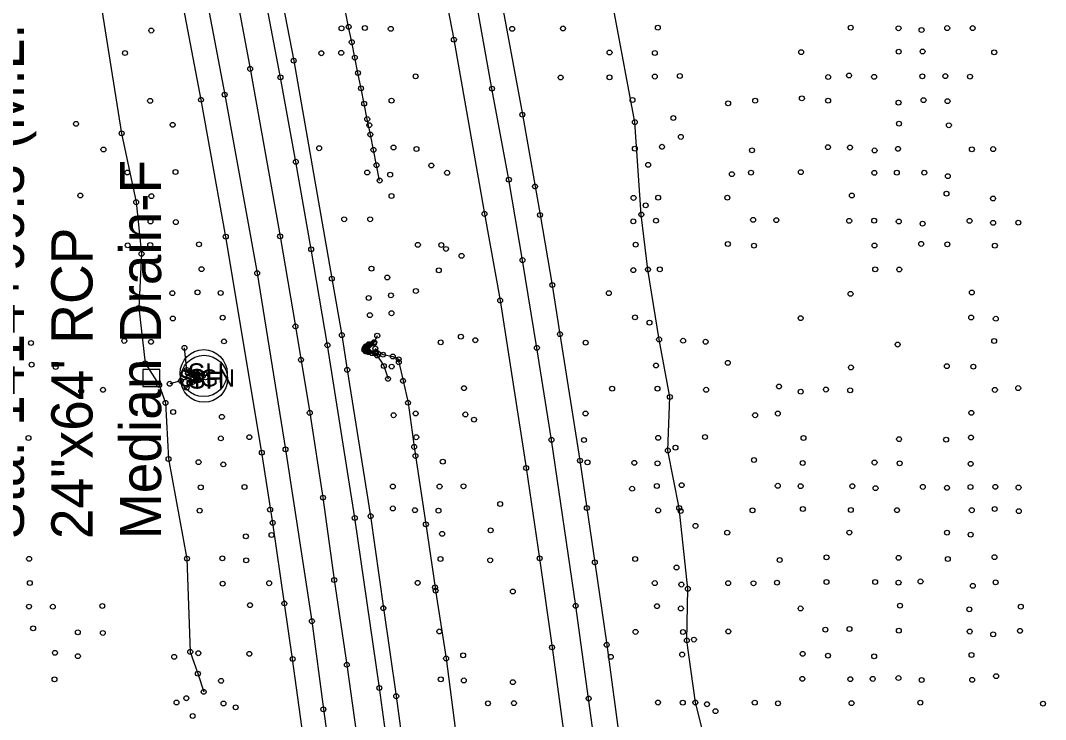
# Model space of a CAD drawing. Extents: x 20503438 to 20508873, y 7964251 to 7984667.
# Drawn here: x 20506477 to 20506895.3, y 7974142.9 to 7974428.1 of the extents above; entities that cross this region are included whole.
import ezdxf

# ---------------------------------------------------------------- set-up
doc = ezdxf.new("R2010")
doc.units = 0
for name, color, linetype in [('SurBreakLine', 7, 'Continuous'), ('SurConcreteSlab', 7, 'Continuous'), ('SurDrainageArrowDown', 7, 'Continuous'), ('SurDrainageArrowUp', 7, 'Continuous'), ('SurEdgeRoadPaved', 7, 'Continuous'), ('SurEdgeShoulderPaved', 7, 'Continuous'), ('SurNaturalCells', 7, 'Continuous'), ('SurPointsNonDTM', 7, 'Continuous'), ('SurRoadPoints', 7, 'Continuous'), ('SurSurveyPoints', 7, 'Continuous'), ('SurTxtDrainage', 7, 'Continuous')]:
    doc.layers.add(name, color=color, linetype=linetype)

msp = doc.modelspace()

# ---------------------------------------------------------------- linework, layer by layer
at = {"layer": 'SurBreakLine'}
for points in [[(20506576.27, 7974776.6), (20506593.8, 7974705.89), (20506609.82, 7974635.75), (20506617.81, 7974599.34), (20506640.03, 7974492.01), (20506653.87, 7974420.35), (20506666.37, 7974349.21), (20506672.75, 7974313.88), (20506683.34, 7974245.52), (20506688.86, 7974208.63), (20506693.93, 7974172.3), (20506703.16, 7974103.94)], [(20506496.44, 7974749.65), (20506513.28, 7974680.82), (20506521.4, 7974646.05), (20506529.3, 7974611.15), (20506530.58, 7974605.33), (20506531.23, 7974602.42), (20506534.44, 7974587.86), (20506543.23, 7974547.26), (20506549.96, 7974513.93), (20506556.42, 7974482.86), (20506563.46, 7974447), (20506570.72, 7974408.4), (20506582.94, 7974340.06), (20506589.19, 7974303.3), (20506595.05, 7974268.01), (20506600.44, 7974233.42), (20506605.04, 7974199.81), (20506610.16, 7974165.22), (20506614.11, 7974136.91)], [(20506622.58, 7974299.5), (20506621.36, 7974296.88), (20506619.19, 7974296.02), (20506617.84, 7974295.09), (20506617.44, 7974294.37), (20506617.3, 7974293.68), (20506617.98, 7974292.98), (20506620.4, 7974292.37), (20506621.98, 7974292.19), (20506622.55, 7974291.45), (20506625.26, 7974287.15), (20506626.99, 7974281.89)], [(20506544.81, 7974278.28), (20506546.06, 7974279.95), (20506548.33, 7974281.05), (20506549.46, 7974281.51), (20506552.46, 7974282.53), (20506552.02, 7974283.94), (20506549.26, 7974283.91), (20506545.43, 7974284.52), (20506544.91, 7974285.49), (20506543.93, 7974294.57)]]:
    msp.add_lwpolyline(points, dxfattribs=at)
at = {"layer": 'SurConcreteSlab'}
for points in [[(20506621.93, 7974292.81), (20506618.97, 7974293.19), (20506618.34, 7974293.51), (20506618.21, 7974294.14), (20506618.28, 7974294.84), (20506619.19, 7974295.49), (20506621.25, 7974296.4), (20506621.18, 7974296.72), (20506619.6, 7974296), (20506618.27, 7974295.21), (20506617.99, 7974294.47), (20506617.85, 7974293.91), (20506618.29, 7974293.26), (20506619.13, 7974292.81), (20506621.62, 7974292.49)], [(20506545.95, 7974280.37), (20506548.76, 7974281.72), (20506549.17, 7974282.28), (20506548.92, 7974283.14), (20506548.08, 7974283.61), (20506545.38, 7974284.07), (20506545.41, 7974284.39), (20506547.58, 7974283.97), (20506548.69, 7974283.59), (20506549.12, 7974283.1), (20506549.31, 7974282.29), (20506548.65, 7974281.39), (20506546.99, 7974280.45), (20506546.02, 7974280.06)]]:
    msp.add_lwpolyline(points, close=True, dxfattribs=at)
at = {"layer": 'SurDrainageArrowDown'}
for points in [[(20506755.78, 7974136.83), (20506752.41, 7974149.78), (20506748.94, 7974175.15), (20506749.34, 7974196.23), (20506745.81, 7974229.19), (20506741.18, 7974252.69), (20506742.02, 7974274.49), (20506737.61, 7974297.98), (20506733.07, 7974326.54), (20506730.36, 7974348.98), (20506727.7, 7974386.63), (20506719.39, 7974431.04), (20506712.14, 7974468.28), (20506707.22, 7974517.82), (20506704.55, 7974534.93), (20506693.74, 7974579.65), (20506669.12, 7974668.51), (20506657.71, 7974715.84), (20506642.35, 7974760.13)], [(20506623.56, 7974362.82), (20506622.3, 7974369.09), (20506621.03, 7974375.37), (20506619.77, 7974381.64), (20506618.51, 7974387.91), (20506617.24, 7974394.19), (20506615.98, 7974400.46), (20506614.71, 7974406.73), (20506613.45, 7974413.01), (20506612.19, 7974419.28), (20506610.92, 7974425.56), (20506609.66, 7974431.83)], [(20506545.45, 7974282.23), (20506542.47, 7974281.12), (20506537.88, 7974279.9)]]:
    msp.add_lwpolyline(points, dxfattribs=at)
at = {"layer": 'SurDrainageArrowUp'}
for points in [[(20506473.78, 7974604.66), (20506480.36, 7974587.19), (20506482.83, 7974571.94), (20506491.28, 7974529.66), (20506491.34, 7974527.7), (20506491.67, 7974526.73), (20506495.97, 7974502.65), (20506497.54, 7974495.64), (20506500.39, 7974485.96), (20506504.21, 7974460.01), (20506510.19, 7974432.48), (20506518.26, 7974382.08), (20506524.19, 7974353.98), (20506526.41, 7974332.93), (20506525.26, 7974310.82), (20506527.84, 7974288.26), (20506533.58, 7974279.38), (20506536.19, 7974272.1), (20506537.43, 7974249.2), (20506544.92, 7974208.5), (20506546.26, 7974170.48), (20506549.4, 7974161.58), (20506551.76, 7974154.15)], [(20506621.79, 7974294.22), (20506624.96, 7974291.77), (20506628.95, 7974291.01), (20506631.32, 7974289.89), (20506631.38, 7974288.67), (20506633.11, 7974281.11), (20506635.15, 7974272.15), (20506637.66, 7974254.12), (20506638.18, 7974250.44), (20506642.45, 7974222.54), (20506646.18, 7974196.79), (20506646.4, 7974195.46), (20506650.69, 7974167.8), (20506657.28, 7974117.15), (20506663.41, 7974066.36)]]:
    msp.add_lwpolyline(points, dxfattribs=at)
at = {"layer": 'SurEdgeRoadPaved'}
for points in [[(20506601.11, 7974767.59), (20506615.26, 7974710.46), (20506618.47, 7974696.62), (20506622.31, 7974680.02), (20506632.02, 7974638.07), (20506640, 7974601.83), (20506647.68, 7974566.23), (20506658.89, 7974511.83), (20506660.04, 7974506.16), (20506662.35, 7974494.84), (20506665.95, 7974475.44), (20506672.19, 7974441.86), (20506681.8, 7974389.72), (20506686.97, 7974360.38), (20506689.01, 7974348.79), (20506694.04, 7974320.19), (20506697.15, 7974300.16), (20506705.32, 7974248.53), (20506708.15, 7974229.18), (20506711.39, 7974206.99), (20506716.24, 7974173.38), (20506725.64, 7974103.3)], [(20506483.51, 7974751.12), (20506492.4, 7974715.32), (20506501, 7974680.2), (20506517.4, 7974609.46), (20506525.13, 7974573.3), (20506532.86, 7974538.45), (20506547.05, 7974468.05), (20506560.33, 7974397.87), (20506573.57, 7974325), (20506585.16, 7974253.12), (20506595.92, 7974182.98), (20506600.61, 7974147.04), (20506605.6, 7974111.5)], [(20506596.29, 7974107.44), (20506588.06, 7974167.58), (20506584.67, 7974190.25), (20506579.93, 7974223.1), (20506575.49, 7974251.78), (20506560.77, 7974339.91), (20506550.66, 7974395.81), (20506534.83, 7974479.46), (20506523.72, 7974534.35), (20506517.1, 7974564.53), (20506511.57, 7974590.47), (20506503.36, 7974626.26), (20506497.68, 7974651.01), (20506492.26, 7974674.18), (20506484.05, 7974708.49), (20506482.06, 7974716.57), (20506481.39, 7974719.26)], [(20506628.34, 7974119.83), (20506623.44, 7974155.73), (20506613.41, 7974225.13), (20506602.26, 7974295.62), (20506595.62, 7974334.77), (20506589.36, 7974370.49), (20506583.07, 7974404.95), (20506570.23, 7974472.96), (20506555.99, 7974542.36), (20506548.57, 7974577.73), (20506532.64, 7974648.96), (20506516.06, 7974719.27)], [(20506713.77, 7974114.92), (20506708.86, 7974151.42), (20506703.58, 7974189.28), (20506693.67, 7974257.02), (20506687.75, 7974294.55), (20506681.88, 7974330.37), (20506676.31, 7974363.19), (20506669.41, 7974400.34), (20506662.81, 7974437.14), (20506657.64, 7974463.61), (20506648.32, 7974511.02), (20506640.98, 7974546.95), (20506633.65, 7974581.85), (20506626.14, 7974616.31), (20506618.24, 7974651.55), (20506601.4, 7974722.56)]]:
    msp.add_lwpolyline(points, dxfattribs=at)
at = {"layer": 'SurEdgeShoulderPaved'}
msp.add_lwpolyline([(20506517.02, 7974741.08), (20506525.96, 7974704.19), (20506534.77, 7974667.21), (20506543.36, 7974630.1), (20506550.98, 7974596.41), (20506559.68, 7974556.88), (20506570.93, 7974500.91), (20506581.3, 7974449.02), (20506588.5, 7974411.74), (20506604.06, 7974322.81), (20506608.12, 7974299.76), (20506610.34, 7974285.59), (20506619.88, 7974225.89), (20506625.09, 7974188.3), (20506630.34, 7974152.37), (20506635.51, 7974114.13)], dxfattribs=at)
at = {"layer": 'SurNaturalCells'}
for centre in [(20506551.75, 7974284.22), (20506551.92, 7974281.91)]:
    msp.add_circle(centre, 9.59, dxfattribs=at)
at = {"layer": 'SurPointsNonDTM'}
for centre in [(20506743.43, 7974388.34), (20506746.47, 7974380.64), (20506738.81, 7974376.61), (20506733.17, 7974369.26), (20506732.14, 7974352.69), (20506733.71, 7974304.81), (20506591.45, 7974289.67), (20506744.31, 7974253.8), (20506752.46, 7974221.88), (20506744.73, 7974204.92), (20506751.83, 7974175.48), (20506760.63, 7974146.29)]:
    msp.add_circle(centre, 1, dxfattribs=at)
at = {"layer": 'SurRoadPoints'}
msp.add_lwpolyline([(20506530.37, 7974278.83), (20506530.37, 7974278.83), (20506533.8, 7974278.83), (20506533.8, 7974285.69), (20506526.94, 7974285.69), (20506526.94, 7974278.83), (20506530.37, 7974278.83)], dxfattribs=at)
at = {"layer": 'SurSurveyPoints'}
for centre in [(20506610.92, 7974425.56), (20506530.36, 7974424.04), (20506608, 7974424.97), (20506617.55, 7974425.09), (20506628.1, 7974424.75), (20506677.63, 7974424.76), (20506698.38, 7974424.91), (20506737.1, 7974425.2), (20506815.82, 7974425.21), (20506835.35, 7974424.98), (20506844.73, 7974424.25), (20506855.21, 7974425.05), (20506865.57, 7974425.04), (20506612.19, 7974419.28), (20506653.87, 7974420.35), (20506519.66, 7974414.86), (20506599.76, 7974414.79), (20506607.9, 7974414.97), (20506613.45, 7974413.01), (20506717.4, 7974415.07), (20506735.88, 7974414.91), (20506795.61, 7974415.22), (20506835.39, 7974415.41), (20506845.15, 7974415.5), (20506874.39, 7974415.16), (20506588.5, 7974411.74), (20506570.72, 7974408.4), (20506583.07, 7974404.95), (20506614.71, 7974406.73), (20506638.24, 7974405.36), (20506697.44, 7974404.87), (20506717.37, 7974404.95), (20506735.89, 7974405.27), (20506746.06, 7974405.52), (20506806.61, 7974405.06), (20506815.14, 7974405.69), (20506825.36, 7974405.16), (20506845.06, 7974405.38), (20506854.44, 7974405.45), (20506864.49, 7974405.25), (20506615.98, 7974400.46), (20506669.41, 7974400.34), (20506560.33, 7974397.87), (20506795.9, 7974396.36), (20506529.88, 7974395.35), (20506550.66, 7974395.81), (20506617.24, 7974394.19), (20506628.44, 7974395.45), (20506726.78, 7974395.7), (20506765.77, 7974394.34), (20506776.81, 7974395.41), (20506806.59, 7974395.43), (20506835.35, 7974394.63), (20506845.55, 7974395.65), (20506855.35, 7974395.22), (20506618.51, 7974387.91), (20506681.8, 7974389.72), (20506499.67, 7974385.96), (20506539.11, 7974385.56), (20506619.33, 7974385.4), (20506727.7, 7974386.63), (20506835.5, 7974386.03), (20506855.89, 7974385.39), (20506518.26, 7974382.08), (20506619.77, 7974381.64), (20506510.84, 7974375.48), (20506598.87, 7974376.02), (20506621.03, 7974375.37), (20506629.23, 7974376.32), (20506638.58, 7974375.7), (20506727.73, 7974375.84), (20506806.52, 7974376.47), (20506815.53, 7974376.28), (20506835.13, 7974375.78), (20506865.27, 7974375.57), (20506873.96, 7974375.67), (20506775.52, 7974375.18), (20506825.56, 7974375.12), (20506589.36, 7974370.49), (20506622.3, 7974369.09), (20506644.66, 7974368.99), (20506520.59, 7974366.1), (20506540.26, 7974366.33), (20506618.5, 7974366.1), (20506623.56, 7974362.82), (20506627.87, 7974365.21), (20506651.1, 7974366.01), (20506676.31, 7974363.19), (20506767.32, 7974365.44), (20506775.12, 7974366.07), (20506795.45, 7974366.25), (20506825.48, 7974365.96), (20506834.65, 7974366.06), (20506845.83, 7974366.02), (20506855.46, 7974364.61), (20506686.97, 7974360.38), (20506501.41, 7974356.71), (20506530.41, 7974356.46), (20506628.38, 7974356.52), (20506727.2, 7974355.74), (20506737.24, 7974355.85), (20506765.47, 7974355.82), (20506816.27, 7974356.72), (20506854.92, 7974357.48), (20506873.91, 7974355.51), (20506524.19, 7974353.98), (20506530.06, 7974346.14), (20506609.07, 7974347.03), (20506619.71, 7974347.03), (20506666.37, 7974349.21), (20506689.01, 7974348.79), (20506727.08, 7974346.19), (20506730.36, 7974348.98), (20506736.34, 7974346.43), (20506775.97, 7974346.8), (20506785.45, 7974346.66), (20506815.22, 7974346.39), (20506825.4, 7974346.44), (20506835.42, 7974346.11), (20506864.33, 7974346.37), (20506540.38, 7974345.87), (20506845.15, 7974345.21), (20506873.93, 7974345.58), (20506884.22, 7974345.63), (20506560.77, 7974339.91), (20506582.94, 7974340.06), (20506520.76, 7974336.38), (20506529.95, 7974336.51), (20506549.83, 7974336.82), (20506595.62, 7974334.77), (20506639.18, 7974336.59), (20506648.75, 7974336.52), (20506650.65, 7974334.92), (20506728.04, 7974336.65), (20506765.7, 7974336.93), (20506776.35, 7974336.25), (20506825.53, 7974336.31), (20506844.57, 7974336.97), (20506855.25, 7974336.82), (20506874.66, 7974336.27), (20506526.41, 7974332.93), (20506657, 7974332.11), (20506681.88, 7974330.37), (20506550.9, 7974326.66), (20506620.21, 7974326.87), (20506647.71, 7974326.2), (20506727.11, 7974326.29), (20506733.07, 7974326.54), (20506737.93, 7974326.57), (20506825.83, 7974326.61), (20506835.63, 7974326.54), (20506573.57, 7974325), (20506604.06, 7974322.81), (20506626.68, 7974323.27), (20506538.98, 7974316.85), (20506549.26, 7974317.2), (20506558.68, 7974316.96), (20506638.37, 7974317.73), (20506694.04, 7974320.19), (20506717.12, 7974316.86), (20506865.25, 7974317.13), (20506619.08, 7974314.92), (20506628.17, 7974315.96), (20506672.75, 7974313.88), (20506815.75, 7974316.58), (20506525.26, 7974310.82), (20506628.4, 7974308.67), (20506539.16, 7974306.54), (20506559.51, 7974306.86), (20506619.59, 7974307.87), (20506727.77, 7974306.98), (20506795.39, 7974306.67), (20506864.97, 7974306.93), (20506875.01, 7974306.43), (20506589.19, 7974303.3), (20506697.15, 7974300.16), (20506481.28, 7974296.53), (20506519.35, 7974297.39), (20506530.25, 7974297.01), (20506560.03, 7974297.18), (20506608.12, 7974299.76), (20506619.19, 7974296.02), (20506619.6, 7974296), (20506621.18, 7974296.72), (20506621.25, 7974296.4), (20506621.36, 7974296.88), (20506622.58, 7974299.5), (20506648.49, 7974296.79), (20506656.73, 7974299.11), (20506662.6, 7974297.65), (20506707.64, 7974296.68), (20506737.61, 7974297.98), (20506747.4, 7974297.45), (20506756.6, 7974297.03), (20506834.97, 7974295.88), (20506874.36, 7974297.36), (20506543.93, 7974294.57), (20506602.26, 7974295.62), (20506617.3, 7974293.68), (20506617.44, 7974294.37), (20506617.84, 7974295.09), (20506617.85, 7974293.91), (20506617.98, 7974292.98), (20506617.99, 7974294.47), (20506618.21, 7974294.14), (20506618.27, 7974295.21), (20506618.28, 7974294.84), (20506618.29, 7974293.26), (20506618.34, 7974293.51), (20506618.97, 7974293.19), (20506619.13, 7974292.81), (20506619.19, 7974295.49), (20506620.4, 7974292.37), (20506621.62, 7974292.49), (20506621.79, 7974294.22), (20506621.93, 7974292.81), (20506621.98, 7974292.19), (20506624.96, 7974291.77), (20506687.75, 7974294.55), (20506481.53, 7974287.7), (20506527.84, 7974288.26), (20506622.55, 7974291.45), (20506628.95, 7974291.01), (20506631.32, 7974289.89), (20506631.38, 7974288.67), (20506765.68, 7974288.42), (20506491.34, 7974286.73), (20506544.91, 7974285.49), (20506545.38, 7974284.07), (20506545.41, 7974284.39), (20506545.43, 7974284.52), (20506547.58, 7974283.97), (20506548.08, 7974283.61), (20506548.69, 7974283.59), (20506549.26, 7974283.91), (20506552.02, 7974283.94), (20506610.34, 7974285.59), (20506625.26, 7974287.15), (20506628.48, 7974286.9), (20506736.35, 7974287.36), (20506815.91, 7974286.55), (20506855.04, 7974287.09), (20506865.87, 7974286.86), (20506533.58, 7974279.38), (20506537.88, 7974279.9), (20506542.47, 7974281.12), (20506545.45, 7974282.23), (20506545.95, 7974280.37), (20506546.02, 7974280.06), (20506546.06, 7974279.95), (20506546.99, 7974280.45), (20506548.33, 7974281.05), (20506548.65, 7974281.39), (20506548.76, 7974281.72), (20506548.92, 7974283.14), (20506549.12, 7974283.1), (20506549.17, 7974282.28), (20506549.31, 7974282.29), (20506549.46, 7974281.51), (20506552.46, 7974282.53), (20506626.99, 7974281.89), (20506633.11, 7974281.11), (20506501.76, 7974276.91), (20506510.68, 7974277.44), (20506544.81, 7974278.28), (20506657.98, 7974278.09), (20506718.44, 7974277.88), (20506736.98, 7974277.89), (20506756.8, 7974277.45), (20506786.56, 7974278.77), (20506795.41, 7974276.64), (20506805.71, 7974277.53), (20506815.58, 7974277.23), (20506874.66, 7974277.38), (20506884.18, 7974278.12), (20506536.19, 7974272.1), (20506635.15, 7974272.15), (20506742.02, 7974274.49), (20506529.28, 7974267.5), (20506539.28, 7974268.37), (20506595.05, 7974268.01), (20506629.26, 7974267.04), (20506638.25, 7974267.78), (20506658.56, 7974267.37), (20506707.61, 7974267.76), (20506776.79, 7974267.04), (20506786.09, 7974267.73), (20506865.04, 7974268.03), (20506559.19, 7974266.38), (20506662.07, 7974265.26), (20506570.37, 7974258.11), (20506756.33, 7974258.15), (20506480.24, 7974257.76), (20506558.77, 7974257.59), (20506637.66, 7974254.12), (20506638.51, 7974258.06), (20506693.67, 7974257.02), (20506706.97, 7974256.93), (20506737.25, 7974257.83), (20506796.53, 7974257.74), (20506835.55, 7974257.27), (20506854.74, 7974257.07), (20506864.9, 7974257.96), (20506575.49, 7974251.78), (20506585.16, 7974253.12), (20506638.18, 7974250.44), (20506741.18, 7974252.69), (20506537.43, 7974249.2), (20506549.67, 7974247.91), (20506559.76, 7974246.98), (20506649.32, 7974248.11), (20506705.32, 7974248.53), (20506708.36, 7974247.82), (20506727.51, 7974247.62), (20506736.99, 7974247.44), (20506776.32, 7974248.76), (20506796.22, 7974247.54), (20506825.55, 7974247.73), (20506835.78, 7974247.44), (20506864.77, 7974247.21), (20506683.34, 7974245.52), (20506550.56, 7974237.63), (20506568.4, 7974237.75), (20506628.96, 7974237.96), (20506648.03, 7974237.94), (20506657.8, 7974238.06), (20506736.71, 7974238.19), (20506746.82, 7974238.5), (20506786.04, 7974238.26), (20506795.37, 7974238.08), (20506816.46, 7974238.07), (20506825.96, 7974237.27), (20506845.23, 7974237.8), (20506855.1, 7974237.45), (20506864.71, 7974237.78), (20506874.84, 7974237.84), (20506884.32, 7974237.53), (20506600.44, 7974233.42), (20506726.59, 7974237.05), (20506628.96, 7974229.02), (20506672.75, 7974230.81), (20506708.15, 7974229.18), (20506745.81, 7974229.19), (20506550.12, 7974228.12), (20506578.86, 7974228.53), (20506613.41, 7974225.13), (20506619.88, 7974225.89), (20506637.97, 7974228.29), (20506647.59, 7974228.08), (20506737.25, 7974228.2), (20506746.41, 7974227.95), (20506775.74, 7974228.24), (20506796.3, 7974228.79), (20506815.85, 7974228.37), (20506834.69, 7974228.3), (20506865.21, 7974228.28), (20506874.55, 7974228.77), (20506884.44, 7974227.91), (20506579.93, 7974223.1), (20506642.45, 7974222.54), (20506568.99, 7974217.61), (20506579.45, 7974218.16), (20506649.05, 7974218.63), (20506668.85, 7974220.05), (20506765.42, 7974219.14), (20506815.27, 7974219.15), (20506855.13, 7974219.11), (20506864.78, 7974218.33), (20506480.51, 7974208.44), (20506544.92, 7974208.5), (20506559.37, 7974208.65), (20506648.37, 7974208.38), (20506688.86, 7974208.63), (20506727.86, 7974208.37), (20506786.81, 7974207.94), (20506805.97, 7974209.04), (20506835.36, 7974208.83), (20506855.45, 7974208.37), (20506874.51, 7974209.12), (20506569.12, 7974207.84), (20506668.69, 7974207.86), (20506711.39, 7974206.99), (20506605.04, 7974199.81), (20506480.82, 7974198.59), (20506559.51, 7974198.29), (20506578.46, 7974198.48), (20506639.09, 7974198.62), (20506646.18, 7974196.79), (20506646.4, 7974195.46), (20506735.85, 7974198.54), (20506746.71, 7974197.93), (20506749.34, 7974196.23), (20506765.8, 7974198.5), (20506776.14, 7974198.47), (20506785.72, 7974198.7), (20506805.93, 7974198.99), (20506825.8, 7974198.98), (20506835.35, 7974198.74), (20506844.32, 7974199.22), (20506865.66, 7974197.44), (20506874.95, 7974198.85), (20506677.92, 7974195.13), (20506480.48, 7974188.95), (20506490.21, 7974188.89), (20506510.4, 7974189.21), (20506570.66, 7974189.52), (20506584.67, 7974190.25), (20506625.09, 7974188.3), (20506703.58, 7974189.28), (20506736.77, 7974189.11), (20506746.51, 7974188.2), (20506795.36, 7974188.2), (20506835.93, 7974189.32), (20506864.22, 7974187.83), (20506885.24, 7974188.9), (20506595.92, 7974182.98), (20506482.13, 7974180.09), (20506647.92, 7974178.82), (20506728.01, 7974178.62), (20506765.87, 7974178.82), (20506805.48, 7974179.54), (20506815.31, 7974179.79), (20506835.45, 7974179.14), (20506864.38, 7974178.76), (20506884.91, 7974179.05), (20506500.38, 7974178.47), (20506510.59, 7974178.2), (20506747.35, 7974178.57), (20506748.94, 7974175.15), (20506873.96, 7974177.65), (20506546.26, 7974170.48), (20506693.93, 7974172.3), (20506716.24, 7974173.38), (20506491.05, 7974170.06), (20506500.43, 7974168.72), (20506539.7, 7974168.43), (20506549.57, 7974169.92), (20506570.38, 7974169.66), (20506588.06, 7974167.58), (20506650.69, 7974167.8), (20506657.67, 7974169.06), (20506717.93, 7974168.43), (20506747.01, 7974169.37), (20506796.2, 7974169.66), (20506806.55, 7974168.93), (20506825.39, 7974168.65), (20506865.14, 7974169.21), (20506610.16, 7974165.22), (20506490.88, 7974159.26), (20506549.4, 7974161.58), (20506558.85, 7974158.67), (20506648.51, 7974159.26), (20506657.93, 7974158.81), (20506677.95, 7974158.1), (20506796.06, 7974159.45), (20506815.65, 7974159.34), (20506824.8, 7974159.44), (20506835.28, 7974159.78), (20506844.75, 7974158.99), (20506865.37, 7974159.07), (20506875.15, 7974160.55), (20506551.76, 7974154.15), (20506623.44, 7974155.73), (20506540.66, 7974149.8), (20506544.68, 7974151.54), (20506559.83, 7974149.39), (20506630.34, 7974152.37), (20506667.76, 7974149.48), (20506678.37, 7974149.55), (20506708.86, 7974151.42), (20506737.15, 7974149.78), (20506747.27, 7974149.75), (20506752.41, 7974149.78), (20506776.66, 7974149.76), (20506786.11, 7974149.47), (20506816.16, 7974149.52), (20506844.21, 7974149.73), (20506894.31, 7974149.35), (20506564.8, 7974147.84), (20506600.61, 7974147.04), (20506757.18, 7974149.1), (20506547.26, 7974144.3)]:
    msp.add_circle(centre, 1, dxfattribs=at)

# ---------------------------------------------------------------- texts
at = {"layer": 'SurNaturalCells'}
for p in [(20506545.23, 7974280.22), (20506545.4, 7974277.91)]:
    msp.add_text('SH', height=7.995, rotation=360, dxfattribs=at).set_placement(p)
at = {"layer": 'SurRoadPoints'}
msp.add_text('SIGN', height=6.995, rotation=360, dxfattribs=at).set_placement((20506541.58, 7974278.76))
at = {"layer": 'SurTxtDrainage'}
for s, p in [('Sta. 1414+99.3 (M.L.', (20506478.38, 7974216.49)), ('Median Drain-F', (20506534.38, 7974216.49)), ('24"x64\' RCP', (20506506.38, 7974216.49))]:
    msp.add_text(s, height=16.8, rotation=90, dxfattribs=at).set_placement(p)

doc.saveas('drawing.dxf')
